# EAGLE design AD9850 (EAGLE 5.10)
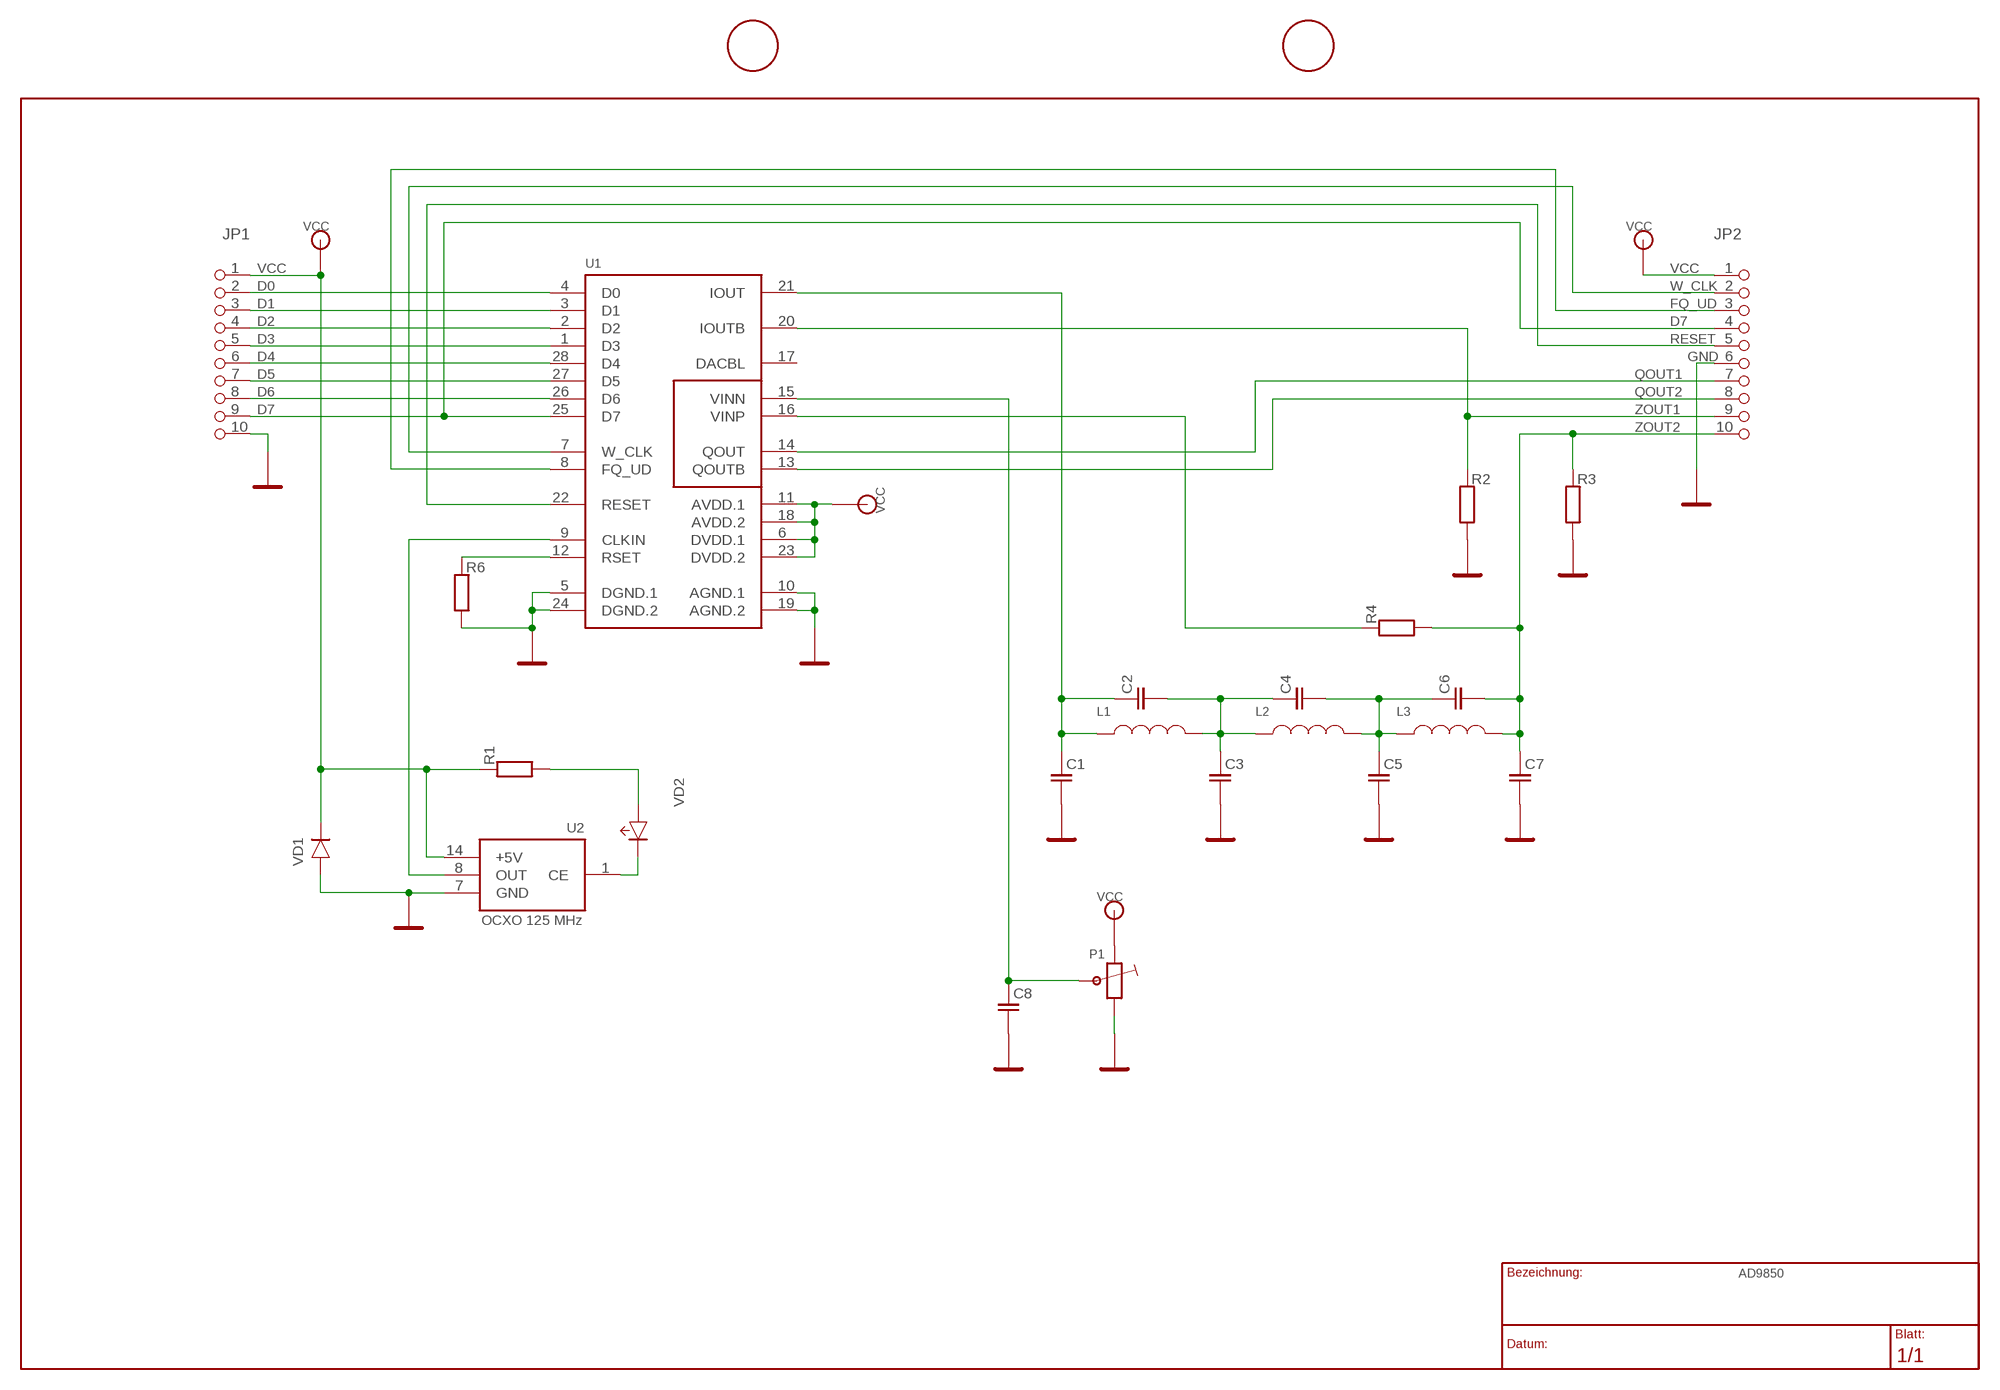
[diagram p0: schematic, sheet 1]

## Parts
C1  SMD-0603  [SOT-0603]
C2  SMD-0603  [SOT-0603]
C3  SMD-0603  [SOT-0603]
C4  SMD-0603  [SOT-0603]
C5  SMD-0603  [SOT-0603]
C6  SMD-0603  [SOT-0603]
C7  SMD-0603  [SOT-0603]
C8  SMD-0603  [SOT-0603]
JP1  PINHD-1X10  [1X10]
JP2  PINHD-1X10  [1X10]
L1  SMD-0603  [SMD-0603]
L2  SMD-0603  [SMD-0603]
L3  SMD-0603  [SMD-0603]
P1  POTI-LG  [POT-L]
R1  SMD-0603  [SMD-0603]
R2  SMD-0603  [SMD-0603]
R3  SMD-0603  [SMD-0603]
R4  SMD-0603  [SMD-0603]
R6  SMD-0603  [SMD-0603]
U1  AD9850  [RS-28]
U2  OCXO 125 MHz  QU-OSZ8  [OSC-KURZ]
VD1  S1DL  [SUB-SMA]
VD2  LED-KLEIN  [LED]

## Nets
CLKIN: U1.9(CLKIN) U2.8(OUT)
D0: JP1.2 U1.4(D0)
D1: JP1.3 U1.3(D1)
D2: JP1.4 U1.2(D2)
D3: JP1.5 U1.1(D3)
D4: JP1.6 U1.28(D4)
D5: JP1.7 U1.27(D5)
D6: JP1.8 U1.26(D6)
D7: JP1.9 JP2.4 U1.25(D7)
FQ_UD: JP2.3 U1.8(FQ_UD)
GND: C1.1 C3.1 C5.1 C7.1 C8.1 JP1.10 JP2.6 P1.1 R2.1 R3.1 R6.1 U1.5(DGND.1) U1.10(AGND.1) U1.19(AGND.2) U1.24(DGND.2) U2.7(GND) VD1.A
N$18: R1.1 VD2.A
N$19: U2.1(CE) VD2.K
N$20: C1.2 C2.2 L1.1 U1.21(IOUT)
N$22: C2.1 C3.2 C4.2 L1.2 L2.1
N$23: C4.1 C5.2 C6.2 L2.2 L3.1
N$24: C8.2 P1.3 U1.15(VINN)
N$25: R4.2 U1.16(VINP)
QOUT1: JP2.7 U1.14(QOUT)
QOUT2: JP2.8 U1.13(QOUTB)
R-SET: R6.2 U1.12(RSET)
RESET: JP2.5 U1.22(RESET)
VCC: JP1.1 JP2.1 P1.2 R1.2 U1.6(DVDD.1) U1.11(AVDD.1) U1.18(AVDD.2) U1.23(DVDD.2) U2.14(+5V) VD1.K
W_CLK: JP2.2 U1.7(W_CLK)
ZOUT1: JP2.9 R2.2 U1.20(IOUTB)
ZOUT2: C6.1 C7.2 JP2.10 L3.2 R3.2 R4.1
Unconnected: U1.17(DACBL)

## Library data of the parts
C1-C8 = C_KERAM:SMD-0603
JP1 JP2 = PINHD-Q:PINHD-1X10
L1-L3 = L:SMD-0603
P1 = R:POTI-LG
R1-R4 R6 = R:SMD-0603
U1 = ANALOG_D:AD9850
U2 = Z_SPECIA:QU-OSZ8
VD1 = DIODEN:S1DL
VD2 = DIODEN:LED-KLEIN

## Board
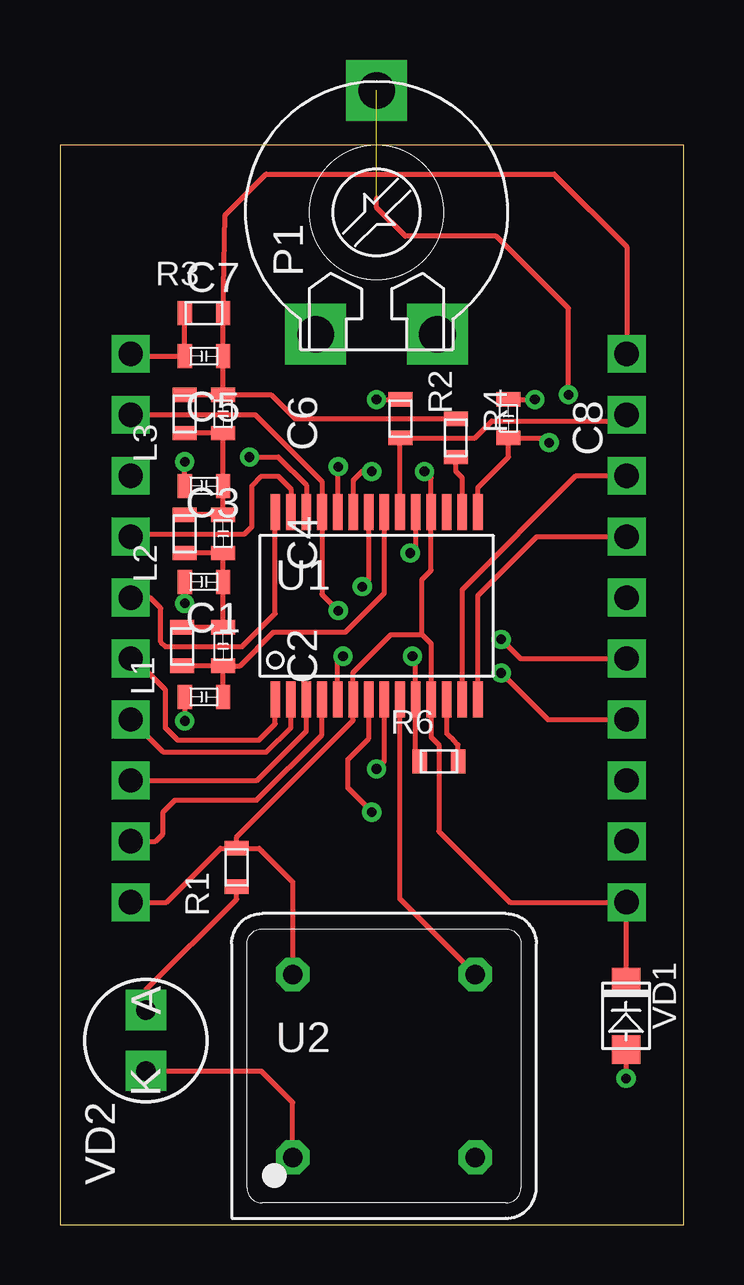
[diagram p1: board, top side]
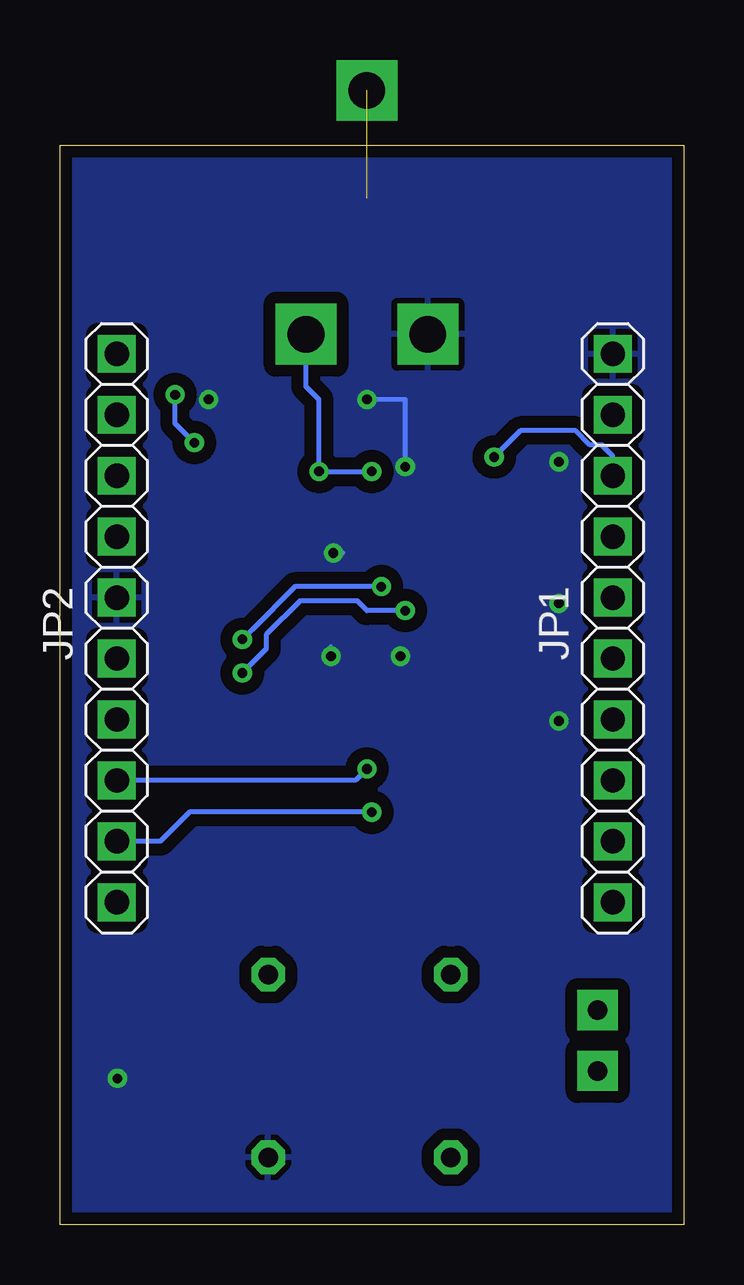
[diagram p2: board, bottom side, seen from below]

Size 26 x 45 mm. Coordinates in mm from the lower left corner, seen from the top.
Outline: 0,0 26,0 26,45 0,45 0,0
Copper layers (1*16): Top 0.035mm / dielectric 1.5mm / Bottom 0.035mm
Design rules "default": minimum track width 0.15mm, minimum drill 0.3mm, track to track 0.15mm, track to pad 0.15mm, pad to pad 0.15mm, via to via 0.15mm, smd to smd 0mil, copper to edge 0.15mm, drill to drill 0.15mm, minimum pad ring 0.15mm, minimum via ring 0.15mm, stop-mask expansion 4mil, vias tented up to drill 0mil, thermal gap 10mil

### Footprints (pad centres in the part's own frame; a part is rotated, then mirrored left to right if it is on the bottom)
SOT-0603 = smd 0.6 x 1: 1 -0.8,0; 2 0.8,0
1X10 = drill 1.016 pad 1.575 square: 1 -11.43,0; 2 -8.89,0; 3 -6.35,0; 4 -3.81,0; 5 -1.27,0; 6 1.27,0; 7 3.81,0; 8 6.35,0; 9 8.89,0; 10 11.43,0
SMD-0603 = smd 0.6 x 1: 1 -0.8,0; 2 0.8,0
POT-L = drill 1.524 pad 2.54 square: 1 -2.54,-5.08; 2 2.54,-5.08; 3 0,5.08
RS-28 = smd 0.4 x 1.5: 1 -4.225,-3.9; 2 -3.575,-3.9; 3 -2.925,-3.9; 4 -2.275,-3.9; 5 -1.625,-3.9; 6 -0.975,-3.9; 7 -0.325,-3.9; 8 0.325,-3.9; 9 0.975,-3.9; 10 1.625,-3.9; 11 2.275,-3.9; 12 2.925,-3.9; 13 3.575,-3.9; 14 4.225,-3.9; 15 4.225,3.9; 16 3.575,3.9; 17 2.925,3.9; 18 2.275,3.9; 19 1.625,3.9; 20 0.975,3.9; 21 0.325,3.9; 22 -0.325,3.9; 23 -0.975,3.9; 24 -1.625,3.9; 25 -2.275,3.9; 26 -2.925,3.9; 27 -3.575,3.9; 28 -4.225,3.9
OSC-KURZ = drill 0.813 pad 1.397 octagon: 1 -3.81,-3.81; 7 3.81,-3.81; 8 3.81,3.81; 14 -3.81,3.81
SUB-SMA = smd 1.2 x 1.2: A 1.4,0; K -1.4,0
LED = drill 0.813 pad 1.676 square: A -1.27,0; K 1.27,0

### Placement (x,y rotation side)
C1  6,22 0 top
C2  6.8,24.1 270 top
C3  6,26.8 0 top
C4  6.8,28.8 270 top
C5  6,30.8 0 top
C6  6.8,33.8 270 top
C7  6,36.2 0 top
C8  18.7,33.6 270 top
JP1  2.95,24.87 90 bottom
JP2  23.63,24.87 90 bottom
L1  5.1,24.1 90 top
L2  5.2,28.8 90 top
L3  5.2,33.8 90 top
P1  13.2,42.2 0 top
R1  7.37,14.89 90 top
R2  14.2,33.6 270 top
R3  6,38 0 top
R4  16.5,32.8 270 top
R6  15.8,19.31 0 top
U1  13.2,25.8 0 top
U2  13.51,6.62 0 top
VD1  23.6,8.7 270 top
VD2  3.58,7.68 270 top

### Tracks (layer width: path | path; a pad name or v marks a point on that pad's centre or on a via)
CLKIN
  Top 0.2: U1.9 14.18,13.57 U2.8
D0
  Top 0.2: U1.4 10.93,20.43 8.2,17.7 4.8,17.7 4.3,17.2 4.3,16.3 3.98,15.98 JP1.2
D1
  Top 0.2: U1.3 10.28,20.57 8.22,18.52 JP1.3
D2
  Top 0.2: U1.2 9.62,20.73 8.6,19.7 4.31,19.7 JP1.4
D3
  Top 0.2: U1.1 8.97,20.88 8.3,20.2 4.9,20.2 4.4,20.7 4.4,22.3 3.1,23.6 JP1.5
D4
  Top 0.2: U1.28 8.97,25.48 7.6,24.1 4.4,24.1 4.2,24.3 4.2,25.7 3.76,26.14 JP1.6
D5
  Top 0.2: U1.27 9.62,30.68 9.1,31.2 8.4,31.2 8,30.8 8,29.1 7.7,28.8 3.07,28.8 JP1.7
D6  (via drill 0.4 pad 0.8)
  Top 0.2: U1.26 10.28,30.82 9.1,32 v7.9,32
  Bottom 0.2: v7.9,32 6.8,33.1 4.5,33.1 3.9,32.5 3.4,32.5 2.95,32.05 JP1.8
D7  (via drill 0.4 pad 0.8)
  Top 0.2: JP1.9 8.14,33.76 10.93,30.98 U1.25 10.93,26.27 v11.6,25.6 | JP2.4 20.34,21.06 v18.4,23
  Bottom 0.2: v18.4,23 17.4,24 17.4,24.6 16,26 13.6,26 13.2,25.6 v11.6,25.6
FQ_UD  (via drill 0.4 pad 0.8)
  Top 0.2: U1.8 13.53,19.32 v13.2,19
  Bottom 0.2: v13.2,19 13.68,18.52 JP2.3
GND  (via drill 0.4 pad 0.8)
  Top 0.2: JP1.10 3.05,36.2 C7.1 R3.1 | C5.1 v5.2,31.8 | VD1.A v23.6,6.1 | R6.1 14.82,19.48 U1.10 14.82,23.57 v14.7,23.7 | U1.5 11.57,23.48 v11.8,23.7 | C3.1 v5.2,25.9 | C1.1 v5.2,21 | U1.24 11.6,29.73 v11.6,31.6 | C8.1 v19.8,34.4 | U1.19 14.82,28.23 v14.6,28 | v13.2,34.4 R2.1
  Bottom 0.2: v5.2,31.8 5.2,31.5 | v23.6,6.1 23.6,6.4 | v14.7,23.7 14.7,24.1 | v11.8,23.7 11.7,23.6 | v5.2,25.9 5.2,26 | v5.2,21 5.2,21.3 | v11.6,31.6 11.6,34.4 v13.2,34.4 | v19.8,34.4 19.6,34.4 | v14.6,28 14.2,28
  pour Bottom (isolate 0.5): 0.4,44.7 25.6,44.7 25.6,0.3 0.4,0.3
N$18
  Top 0.2: VD2.A 3.58,9.78 7.37,13.57 R1.1
N$19
  Top 0.2: U2.1 9.7,5.1 8.4,6.4 VD2.K
N$20
  Top 0.2: C2.2 L1.1 | C1.2 C2.2 | C2.2 7.5,23.3 8.9,24.7 11.9,24.7 12.2,25 13.53,26.32 U1.21
N$22
  Top 0.2: L2.1 C4.2 C3.2 C2.1 L1.2
N$23
  Top 0.2: L3.1 C6.2 C5.2 C4.1 L2.2
N$24  (via drill 0.4 pad 0.8)  (1 unrouted)
  Top 0.2: U1.15 17.43,30.73 18.7,32 C8.2 20.2,32.8 v20.4,32.6 | v21.2,34.6 21.2,38.2 18.2,41.2 14.4,41.2 13.2,42.4 13.2,42.8
  Bottom 0.2: v20.4,32.6 21.2,33.4 v21.2,34.6
N$25
  Top 0.2: U1.16 16.77,31.12 16.5,31.4 R4.2
QOUT1
  Top 0.2: U1.14 17.43,26.23 19.88,28.68 JP2.7
QOUT2
  Top 0.2: U1.13 16.77,26.48 21.52,31.22 JP2.8
R-SET
  Top 0.2: R6.2 16.6,20 16.4,20.2 16.2,20.4 16.12,20.48 U1.12
RESET  (via drill 0.4 pad 0.8)
  Top 0.2: U1.22 12.88,26.88 v12.6,26.6 | JP2.5 19.2,23.6 v18.4,24.4
  Bottom 0.2: v12.6,26.6 16.2,26.6 18,24.8 v18.4,24.4
VCC  (via drill 0.4 pad 0.8)
  Top 0.2: VD1.K 23.6,13.41 JP2.1 18.76,13.44 15.8,16.4 15.8,20 15.47,20.32 U1.11 15.47,24.23 15.1,24.6 | 15.1,24.6 13.8,24.6 12.22,23.02 U1.6 12.22,21.02 7.37,16.17 R1.2 | 15.1,24.6 15.1,26.9 15.47,27.27 U1.18 15.47,31.12 v15.2,31.4 | JP1.1 4.44,13.44 6.69,15.69 R1.2 | U2.14 9.7,14.3 8.31,15.69 R1.2 | U1.23 12.22,31.02 12.6,31.4 v13,31.4
  Bottom 0.2: P1.2 15.74,34.94 15.2,34.4 v15.2,31.4 v13,31.4
W_CLK  (via drill 0.4 pad 0.8)
  Top 0.2: U1.7 12.88,20.27 12,19.4 12,18.2 v13,17.2
  Bottom 0.2: v13,17.2 20.6,17.2 21.82,15.98 JP2.2
ZOUT1
  Top 0.2: U1.20 14.18,32.77 R2.2 17.3,32.8 18,33.5 23.37,33.5 JP2.9
ZOUT2
  Top 0.2: JP2.10 23.63,40.77 20.6,43.8 8.6,43.8 6.88,42.08 R3.2 C7.2 C6.1 | L3.2 C6.1 | C6.1 8.8,34.6 9.8,33.6 R4.1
